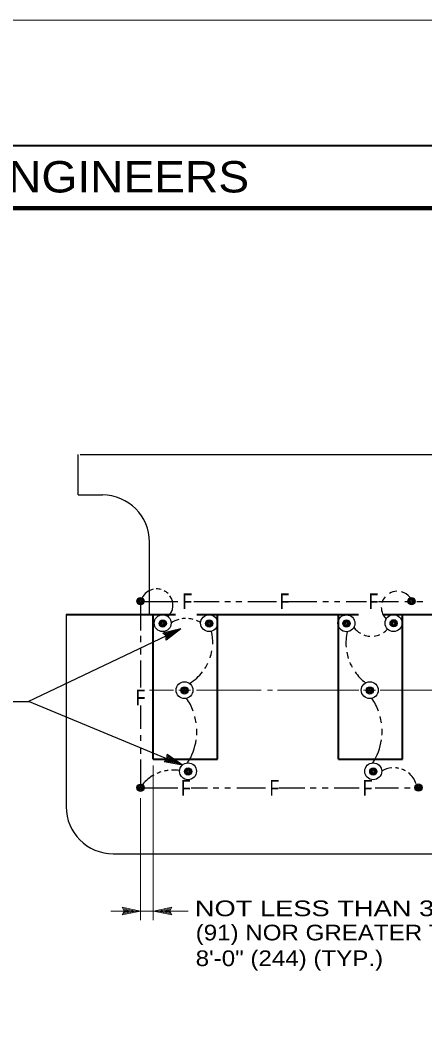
# Model space of a CAD drawing. Extents: x -39.6 to 16.1, y -17.6 to 34.
# Drawn here: x -21.04 to -17.81, y 4.44 to 12.41 of the extents above; entities that cross this region are included whole.
import ezdxf
from ezdxf.enums import TextEntityAlignment as Align

# ---------------------------------------------------------------- set-up
doc = ezdxf.new("R2010")
doc.units = 0
doc.header["$LTSCALE"] = 0.05
doc.layers.add('1', color=7, linetype='Continuous', lineweight=13)
doc.layers.add('2', color=7, linetype='Continuous', lineweight=13)

msp = doc.modelspace()

# ---------------------------------------------------------------- linework, layer by layer
at = {"layer": '1', "lineweight": 25}
for p, q in [((-20.57221, 8.62142), (-20.57221, 8.94342)), ((-20.55621, 8.94342), (-14.22521, 8.94342)), ((-20.57221, 8.62142), (-20.37821, 8.62142)), ((-20.00321, 7.66742), (-20.00321, 8.24642)), ((-20.07621, 7.77342), (-19.77621, 7.77342)), ((-20.07621, 7.77342), (-20.07621, 7.54042)), ((-19.65021, 7.77342), (-19.44721, 7.77342)), ((-19.40221, 7.77342), (-19.35721, 7.77342)), ((-19.31621, 7.77342), (-19.26721, 7.77342)), ((-19.22021, 7.77342), (-18.99021, 7.77342)), ((-18.89221, 7.77342), (-18.66921, 7.77342)), ((-18.62221, 7.77342), (-18.57621, 7.77342)), ((-18.52821, 7.77342), (-18.48621, 7.77342)), ((-18.43721, 7.77342), (-18.27421, 7.77342)), ((-18.17821, 7.77342), (-18.01921, 7.77342)), ((-17.96921, 7.77342), (-17.91821, 7.77342)), ((-17.87321, 7.77342), (-17.82621, 7.77342)), ((-20.66721, 7.66742), (-20.66721, 6.13642)), ((-20.97021, 6.97442), (-19.75421, 7.55342)), ((-20.07621, 7.49842), (-20.07621, 7.44842)), ((-19.75421, 7.55342), (-19.89721, 7.51942)), ((-19.78721, 7.53742), (-19.88121, 7.51542)), ((-19.86421, 7.50142), (-19.88121, 7.51542)), ((-19.75421, 7.55342), (-19.87121, 7.46342)), ((-19.78721, 7.53742), (-19.86421, 7.47942)), ((-19.82021, 7.52242), (-19.86421, 7.51042)), ((-19.85721, 7.50442), (-19.86421, 7.51042)), ((-19.86421, 7.47942), (-19.86421, 7.50142)), ((-19.85621, 7.49342), (-19.85721, 7.50442)), ((-19.82021, 7.52242), (-19.85621, 7.49342)), ((-20.07621, 7.39942), (-20.07621, 7.34842)), ((-20.07621, 7.30142), (-20.07621, 7.08742)), ((-20.96321, 6.97442), (-19.74121, 6.46842)), ((-20.07621, 6.94242), (-20.07621, 6.75642)), ((-20.07621, 6.70542), (-20.07621, 6.66042)), ((-20.07621, 6.60942), (-20.07621, 6.55842)), ((-19.74121, 6.46842), (-19.86221, 6.55242)), ((-20.07621, 6.51142), (-20.07621, 6.28642)), ((-19.74121, 6.46842), (-19.88621, 6.49442)), ((-19.87021, 6.50042), (-19.85421, 6.51542)), ((-19.77521, 6.48242), (-19.87021, 6.50042)), ((-19.77521, 6.48242), (-19.85421, 6.53742)), ((-19.85421, 6.51542), (-19.85421, 6.53742)), ((-19.85421, 6.50442), (-19.84621, 6.51242)), ((-19.80821, 6.49642), (-19.85421, 6.50442)), ((-19.80821, 6.49642), (-19.84721, 6.52142)), ((-19.84621, 6.51242), (-19.84721, 6.52142)), ((-20.07621, 6.28642), (-19.77621, 6.28642)), ((-19.67121, 6.28642), (-19.54121, 6.28642)), ((-19.49621, 6.28642), (-19.45121, 6.28642)), ((-19.40221, 6.28642), (-19.35721, 6.28642)), ((-19.30621, 6.28642), (-19.07821, 6.28642)), ((-18.97321, 6.28642), (-18.76521, 6.28642)), ((-18.72321, 6.28642), (-18.67421, 6.28642)), ((-18.62721, 6.28642), (-18.57821, 6.28642)), ((-18.53121, 6.28642), (-18.33121, 6.28642)), ((-18.20521, 6.28642), (-18.01921, 6.28642)), ((-17.97221, 6.28642), (-17.92721, 6.28642)), ((-17.88421, 6.28642), (-17.83721, 6.28642)), ((-20.29221, 5.76142), (-14.66821, 5.76142))]:
    msp.add_line(p, q, dxfattribs=at)
at = {"layer": '1', "lineweight": 40}
for p, q in [((-20.66721, 7.66742), (-19.79721, 7.66742)), ((-19.97321, 6.51442), (-19.97321, 7.66742)), ((-19.62521, 7.66742), (-18.33721, 7.66742)), ((-19.46221, 6.51442), (-19.46221, 7.66742)), ((-18.49721, 6.51442), (-18.49721, 7.66742)), ((-18.13621, 7.66742), (-16.87721, 7.66742)), ((-17.98621, 6.51442), (-17.98621, 7.66742)), ((-19.97321, 6.51442), (-19.46221, 6.51442)), ((-18.49721, 6.51442), (-17.98621, 6.51442))]:
    msp.add_line(p, q, dxfattribs=at)
at = {"layer": '1'}
for p, q in [((-20.00421, 7.06442), (-19.81221, 7.06442)), ((-19.77021, 7.06442), (-19.67521, 7.06442)), ((-19.62821, 7.06442), (-19.11221, 7.06442)), ((-19.06421, 7.06442), (-19.02421, 7.06442)), ((-18.98221, 7.06442), (-18.33421, 7.06442)), ((-18.29821, 7.06442), (-18.20321, 7.06442)), ((-18.16521, 7.06442), (-17.61021, 7.06442)), ((-19.97321, 6.46442), (-19.97321, 5.23142)), ((-20.07621, 6.20542), (-20.07621, 5.23142)), ((-20.07621, 5.30442), (-20.22021, 5.33542)), ((-20.07621, 5.30442), (-20.22021, 5.27342)), ((-20.11321, 5.30442), (-20.20721, 5.32442)), ((-20.19821, 5.30442), (-20.20721, 5.32442)), ((-20.11321, 5.30442), (-20.20721, 5.28442)), ((-20.20721, 5.28442), (-20.19821, 5.30442)), ((-20.14921, 5.30442), (-20.19421, 5.31342)), ((-20.19021, 5.30442), (-20.19421, 5.31342)), ((-20.14921, 5.30442), (-20.19421, 5.29442)), ((-20.19421, 5.29442), (-20.19021, 5.30442)), ((-19.97021, 5.30442), (-19.82621, 5.33542)), ((-19.97021, 5.30442), (-19.82621, 5.27342)), ((-19.93321, 5.30442), (-19.83921, 5.32442)), ((-19.93321, 5.30442), (-19.83921, 5.28442)), ((-19.89721, 5.30442), (-19.85221, 5.31442)), ((-19.89721, 5.30442), (-19.85221, 5.29542)), ((-19.85221, 5.31442), (-19.85621, 5.30442)), ((-19.85621, 5.30442), (-19.85221, 5.29542)), ((-19.83921, 5.32442), (-19.84821, 5.30442)), ((-19.84821, 5.30442), (-19.83921, 5.28442))]:
    msp.add_line(p, q, dxfattribs=at)
for points in [[(-25.89821, 12.40842), (16.10179, 12.40842), (16.10179, -17.59158)], [(-20.31121, 5.30442), (-20.07621, 5.30442), (-19.97021, 5.30442), (-19.69621, 5.30442)], [(-20.22021, 5.27342), (-20.20621, 5.30442), (-20.22021, 5.33542)], [(-19.82621, 5.33542), (-19.84021, 5.30442), (-19.82621, 5.27342)]]:
    msp.add_lwpolyline(points, dxfattribs=at)
at = {"layer": '1', "lineweight": 40}
msp.add_lwpolyline([(-24.89821, -16.59158), (-24.89821, 11.40842), (15.10179, 11.40842), (15.10179, -16.59158)], close=True, dxfattribs=at)
at = {"layer": '1', "lineweight": 90}
msp.add_lwpolyline([(-23.39821, 10.90842), (14.60179, 10.90842), (14.60179, -16.09158), (-23.39821, -16.09158)], close=True, dxfattribs=at)
at = {"layer": '1', "lineweight": 25}
for points in [[(-19.87121, 7.46342), (-19.87121, 7.49742), (-19.89721, 7.51942)], [(-19.88621, 6.49442), (-19.86121, 6.51842), (-19.86221, 6.55242)]]:
    msp.add_lwpolyline(points, dxfattribs=at)
for centre, radius in [((-20.07483, 7.77448), 0.02891), ((-20.07483, 7.77448), 0.02242), ((-20.07483, 7.77448), 0.01644), ((-20.07483, 7.77448), 0.0083), ((-17.91583, 7.77548), 0.02891), ((-17.91583, 7.77548), 0.02242), ((-17.91583, 7.77548), 0.01644), ((-17.91583, 7.77548), 0.0083), ((-19.89821, 7.59942), 0.06748), ((-19.52821, 7.59942), 0.06748), ((-18.43421, 7.59842), 0.06748), ((-18.05821, 7.60042), 0.06748), ((-19.89783, 7.59748), 0.02891), ((-19.89783, 7.59748), 0.02242), ((-19.89783, 7.59748), 0.01644), ((-19.89783, 7.59748), 0.0083), ((-19.52783, 7.59748), 0.02891), ((-19.52783, 7.59748), 0.02242), ((-19.52783, 7.59748), 0.01644), ((-19.52783, 7.59748), 0.0083), ((-18.43383, 7.59648), 0.02891), ((-18.43383, 7.59648), 0.02242), ((-18.43383, 7.59648), 0.01644), ((-18.43383, 7.59648), 0.0083), ((-18.05783, 7.59848), 0.02891), ((-18.05783, 7.59848), 0.02242), ((-18.05783, 7.59848), 0.01644), ((-18.05783, 7.59848), 0.0083), ((-19.72421, 7.06542), 0.06748), ((-18.24821, 7.06542), 0.06748), ((-19.72383, 7.06348), 0.02891), ((-19.72383, 7.06348), 0.02242), ((-19.72383, 7.06348), 0.01644), ((-19.72383, 7.06348), 0.0083), ((-18.24783, 7.06348), 0.02891), ((-18.24783, 7.06348), 0.02242), ((-18.24783, 7.06348), 0.01644), ((-18.24783, 7.06348), 0.0083), ((-19.69621, 6.41842), 0.06748), ((-18.22021, 6.41842), 0.06748), ((-19.69583, 6.41648), 0.02891), ((-19.69583, 6.41648), 0.02242), ((-19.69583, 6.41648), 0.01644), ((-19.69583, 6.41648), 0.0083), ((-18.21983, 6.41648), 0.02891), ((-18.21983, 6.41648), 0.02242), ((-18.21983, 6.41648), 0.01644), ((-18.21983, 6.41648), 0.0083), ((-20.07483, 6.28748), 0.02891), ((-20.07483, 6.28748), 0.02242), ((-20.07483, 6.28748), 0.01644), ((-17.85983, 6.28848), 0.02891), ((-17.85983, 6.28848), 0.02242), ((-17.85983, 6.28848), 0.01644), ((-20.07483, 6.28748), 0.0083), ((-17.85983, 6.28848), 0.0083)]:
    msp.add_circle(centre, radius, dxfattribs=at)
for centre, radius, start, end in [((-20.37821, 8.24642), 0.375, 0, 90), ((-19.94599, 7.74358), 0.12937, 102.44637, 153.93879), ((-19.94599, 7.74358), 0.12937, 74.00466, 91.42946), ((-19.94599, 7.74358), 0.12937, 45.65406, 62.08348), ((-19.94599, 7.74358), 0.12937, 314.56801, 34.8809), ((-18.02821, 7.72558), 0.12812, 92.31217, 119.67381), ((-18.02821, 7.72558), 0.12812, 37.97304, 74.64705), ((-18.02821, 7.72558), 0.12812, 138.45731, 163.45632), ((-18.02821, 7.72558), 0.12812, 180.07346, 226.00139), ((-19.71172, 7.42615), 0.21129, 105.48591, 124.43664), ((-19.71172, 7.42615), 0.21129, 90.95875, 99.53474), ((-19.71172, 7.42615), 0.21129, 74.50627, 84.34737), ((-19.71172, 7.42615), 0.21129, 56.53445, 66.70252), ((-19.88468, 7.44786), 0.38532, 357.53753, 12.98094), ((-18.04302, 7.43955), 0.39502, 166.55144, 184.64806), ((-18.23512, 7.66682), 0.17235, 215.62869, 239.35965), ((-18.23512, 7.66682), 0.17235, 249.22563, 265.63288), ((-18.23512, 7.66682), 0.17235, 277.50113, 292.89982), ((-18.23512, 7.66682), 0.17235, 303.86286, 318.41281), ((-19.88468, 7.44786), 0.38532, 341.05506, 349.62884), ((-18.04302, 7.43955), 0.39502, 190.46253, 197.79365), ((-19.88468, 7.44786), 0.38532, 326.87085, 334.40978), ((-18.04302, 7.43955), 0.39502, 202.86164, 208.84607), ((-19.88468, 7.44786), 0.38532, 301.52468, 322.33865), ((-18.04302, 7.43955), 0.39502, 215.36971, 232.91665), ((-20.09474, 6.73683), 0.46868, 20.02769, 34.22173), ((-18.61874, 6.73683), 0.46868, 20.02769, 34.22173), ((-20.09474, 6.73683), 0.46868, 8.31283, 14.59112), ((-18.61874, 6.73683), 0.46868, 8.31283, 14.59112), ((-20.09474, 6.73683), 0.46868, 356.16372, 2.37301), ((-18.61874, 6.73683), 0.46868, 356.16372, 2.37301), ((-20.09474, 6.73683), 0.46868, 327.5582, 351.70708), ((-18.61874, 6.73683), 0.46868, 327.5582, 351.70708), ((-19.81172, 6.10375), 0.32501, 118.72926, 139.59523), ((-19.81172, 6.10375), 0.32501, 107.92487, 113.92254), ((-19.81172, 6.10375), 0.32501, 97.47916, 103.37637), ((-19.81172, 6.10375), 0.32501, 81.77293, 92.91687), ((-18.05655, 6.2583), 0.18789, 94.47848, 120.9597), ((-18.05655, 6.2583), 0.18789, 77.27723, 85.92094), ((-18.05655, 6.2583), 0.18789, 60.63503, 69.93049), ((-18.05655, 6.2583), 0.18789, 18.33976, 51.90287), ((-20.29221, 6.13642), 0.375, 180, 270)]:
    msp.add_arc(centre, radius, start, end, dxfattribs=at)
at = {"layer": '2', "lineweight": 25}
msp.add_line((-22.34121, 6.97442), (-20.96321, 6.97442), dxfattribs=at)

# ---------------------------------------------------------------- texts
at = {"layer": '1'}
for s, height, width, p in [('CORPS OF ENGINEERS', 0.25, 1.1, (-23.39821, 11.03342)), ('NOT LESS THAN 3\'-0"', 0.125, 1.3, (-19.64221, 5.26342)), ('(91) NOR GREATER THAN', 0.125, 1.15, (-19.63521, 5.07042)), ('8\'-0" (244) (TYP.)', 0.125, 1.15, (-19.63521, 4.86542))]:
    msp.add_text(s, height=height, dxfattribs=dict(at, width=width)).set_placement(p)
at = {"layer": '1', "width": 0.75}
for p in [(-19.70171, 7.71142), (-18.92671, 7.71142), (-18.21771, 7.71142), (-20.07371, 6.94542), (-19.71271, 6.22442), (-19.00771, 6.22442), (-18.26471, 6.22442)]:
    msp.add_text('F', height=0.125, dxfattribs=at).set_placement(p, align=Align.CENTER)

doc.saveas('drawing.dxf')
